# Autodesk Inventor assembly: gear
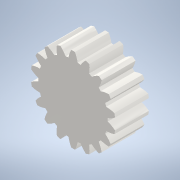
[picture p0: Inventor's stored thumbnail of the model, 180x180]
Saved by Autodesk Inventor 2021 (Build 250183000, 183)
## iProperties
Created: 2021-07
Part Number: gear
Document SubType Name: Assembly
Designer: adams
Author: adams
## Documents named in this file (3)
- C:\Users\adams\Documents\cannon\cymbals\gear.iam
- C:\Users\adams\Documents\cannon\cymbals\gear\Design Accelerator\Spur Gears1.iam
- C:\Users\adams\Documents\cannon\cymbals\gear\Design Accelerator\Spur Gears2.iam
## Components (2 placed, 1 different names)
1. Spur Gears:1 [sub-assembly]
2. Spur Gears:2 [sub-assembly]
